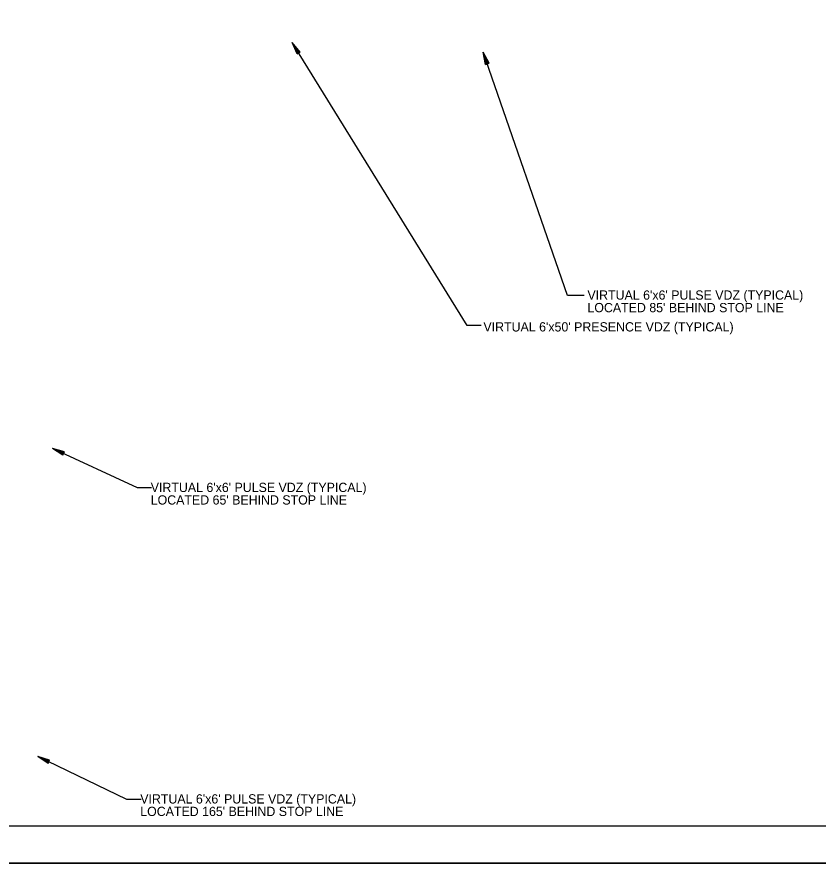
# Model space of a CAD drawing. Extents: x 659404 to 660404, y 642315 to 642955.
# Drawn here: x 659898.9 to 660158.6, y 642315.1 to 642589.4 of the extents above; entities that cross this region are included whole.
import ezdxf

# ---------------------------------------------------------------- set-up
doc = ezdxf.new("R2010")
doc.units = 0
for name, color, linetype in [('R_Border', 7, 'Continuous'), ('R_No Plot', 7, 'Continuous'), ('T_Drafting', 7, 'Continuous')]:
    doc.layers.add(name, color=color, linetype=linetype)

msp = doc.modelspace()

# ---------------------------------------------------------------- linework, layer by layer
at = {"layer": 'R_Border'}
msp.add_line((660389.43, 642327.08), (659440.89, 642327.08), dxfattribs=at)
at = {"layer": 'R_No Plot'}
msp.add_line((659403.69, 642315.15), (660403.69, 642315.15), dxfattribs=at)
msp.add_lwpolyline([(659403.67, 642955.15), (660403.69, 642955.15), (660403.69, 642315.13), (659403.67, 642315.13)], close=True, dxfattribs=at)
at = {"layer": 'T_Drafting'}
for p, q in [((660044.8, 642489.37), (659988.13, 642581.06)), ((659989.72, 642577.35), (659988.13, 642581.06)), ((659990.74, 642577.98), (659988.13, 642581.06)), ((659989.81, 642577.4), (659988.48, 642580.5)), ((659990.66, 642577.92), (659988.48, 642580.5)), ((659990.57, 642577.87), (659988.84, 642579.91)), ((659989.89, 642577.45), (659988.84, 642579.91)), ((659989.98, 642577.51), (659989.19, 642579.34)), ((659990.48, 642577.82), (659989.19, 642579.34)), ((659990.4, 642577.77), (659989.55, 642578.77)), ((659990.07, 642577.56), (659989.55, 642578.77)), ((659989.72, 642577.35), (659990.74, 642577.98)), ((659990.31, 642577.71), (659989.9, 642578.2)), ((659990.15, 642577.61), (659989.9, 642578.2)), ((660050.79, 642573.94), (660050.05, 642577.92)), ((660051.92, 642574.34), (660050.05, 642577.92)), ((660077.33, 642499.1), (660050.05, 642577.92)), ((660050.88, 642573.98), (660050.27, 642577.29)), ((660051.83, 642574.3), (660050.27, 642577.29)), ((660051.73, 642574.27), (660050.49, 642576.64)), ((660050.98, 642574.01), (660050.49, 642576.64)), ((660051.07, 642574.04), (660050.71, 642576.01)), ((660051.64, 642574.24), (660050.71, 642576.01)), ((660050.79, 642573.94), (660051.92, 642574.34)), ((660051.54, 642574.2), (660050.93, 642575.37)), ((660051.17, 642574.08), (660050.93, 642575.37)), ((660051.45, 642574.17), (660051.15, 642574.74)), ((660051.27, 642574.11), (660051.15, 642574.74)), ((660082.76, 642499.1), (660077.33, 642499.1)), ((660049.39, 642489.37), (660044.8, 642489.37)), ((659937.91, 642436.71), (659910.39, 642449.52)), ((659913.76, 642447.29), (659910.39, 642449.52)), ((659914.27, 642448.38), (659910.39, 642449.52)), ((659913.8, 642447.38), (659911, 642449.24)), ((659914.23, 642448.29), (659911, 642449.24)), ((659914.18, 642448.2), (659911.62, 642448.95)), ((659913.85, 642447.48), (659911.62, 642448.95)), ((659913.89, 642447.57), (659912.22, 642448.67)), ((659914.14, 642448.11), (659912.22, 642448.67)), ((659914.1, 642448.01), (659912.84, 642448.38)), ((659913.93, 642447.66), (659912.84, 642448.38)), ((659914.06, 642447.92), (659913.44, 642448.1)), ((659913.98, 642447.75), (659913.44, 642448.1)), ((659913.76, 642447.29), (659914.27, 642448.38)), ((659942.5, 642436.71), (659937.91, 642436.71)), ((659934.51, 642335.76), (659905.61, 642349.64)), ((659908.96, 642347.37), (659905.61, 642349.64)), ((659909.48, 642348.45), (659905.61, 642349.64)), ((659909, 642347.46), (659906.22, 642349.35)), ((659909.44, 642348.36), (659906.22, 642349.35)), ((659909.39, 642348.27), (659906.84, 642349.05)), ((659909.05, 642347.55), (659906.84, 642349.05)), ((659909.09, 642347.64), (659907.44, 642348.76)), ((659909.35, 642348.18), (659907.44, 642348.76)), ((659909.3, 642348.08), (659908.05, 642348.47)), ((659909.13, 642347.73), (659908.05, 642348.47)), ((659908.96, 642347.37), (659909.48, 642348.45)), ((659909.26, 642347.99), (659908.65, 642348.18)), ((659909.18, 642347.82), (659908.65, 642348.18)), ((659939.1, 642335.76), (659934.51, 642335.76))]:
    msp.add_line(p, q, dxfattribs=at)

# ---------------------------------------------------------------- texts
for s, p in [("VIRTUAL 6'x6' PULSE VDZ (TYPICAL)", (660083.83, 642497.73)), ("LOCATED 85' BEHIND STOP LINE", (660083.83, 642493.66)), ("VIRTUAL 6'x50' PRESENCE VDZ (TYPICAL)", (660050.11, 642487.42)), ("VIRTUAL 6'x6' PULSE VDZ (TYPICAL)", (659942.25, 642435.39)), ("LOCATED 65' BEHIND STOP LINE", (659942.25, 642431.33)), ("VIRTUAL 6'x6' PULSE VDZ (TYPICAL)", (659938.85, 642334.44)), ("LOCATED 165' BEHIND STOP LINE", (659938.85, 642330.38))]:
    msp.add_text(s, height=3, dxfattribs=at).set_placement(p)

doc.saveas('drawing.dxf')
